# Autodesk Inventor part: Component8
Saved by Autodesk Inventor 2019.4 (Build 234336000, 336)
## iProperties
Created: 2020-06
Part Number: Component8
Material: Generic
Document SubType Name: Modeling
Designer: Administrator
Density: 1 g/cm^3
Appearance: Default
Title: Component8
Author: Administrator
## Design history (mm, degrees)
